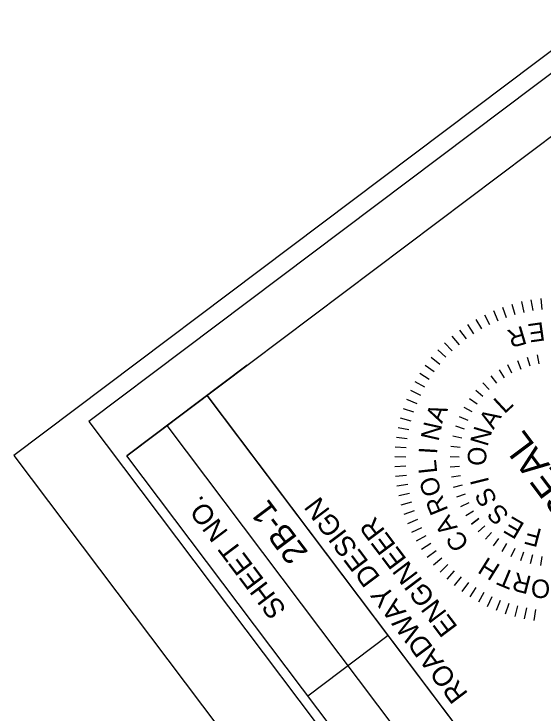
# Model space of a CAD drawing. Extents: x 1262917 to 1264804, y 775326 to 777329.
# Drawn here: x 1262916.5 to 1263048.7, y 776605.9 to 776780.7 of the extents above; entities that cross this region are included whole.
import ezdxf

# ---------------------------------------------------------------- set-up
doc = ezdxf.new("R2010")
doc.units = 0
for name, color, linetype in [('Default', 7, 'Continuous'), ('Sheet Data Field CELL', 7, 'Continuous'), ('Sheet Plan CELL', 7, 'Continuous'), ('Sheet Plot Border Inside CELL', 7, 'Continuous'), ('Sheet Plot Border Outside CELL', 7, 'Continuous'), ('Sheet Typical CELL', 7, 'Continuous')]:
    doc.layers.add(name, color=color, linetype=linetype)

msp = doc.modelspace()

# ---------------------------------------------------------------- linework, layer by layer
at = {"layer": 'Default'}
for p, q in [((1263045.47, 776709.34), (1263045.91, 776706.62)), ((1263047.9, 776709.66), (1263048.17, 776706.92)), ((1263038.38, 776707.52), (1263039.31, 776704.92)), ((1263040.7, 776708.27), (1263041.47, 776705.61)), ((1263043.07, 776708.87), (1263043.68, 776706.18)), ((1263033.88, 776705.6), (1263035.11, 776703.13)), ((1263036.09, 776706.62), (1263037.18, 776704.09)), ((1263031.72, 776704.44), (1263033.1, 776702.05)), ((1263029.64, 776703.15), (1263031.17, 776700.85)), ((1263027.65, 776701.74), (1263029.3, 776699.54)), ((1263023.92, 776698.57), (1263025.83, 776696.58)), ((1263025.73, 776700.21), (1263027.52, 776698.11)), ((1263022.21, 776696.83), (1263024.24, 776694.96)), ((1263020.61, 776694.98), (1263022.74, 776693.23)), ((1263044.55, 776695.01), (1263045.19, 776692.8)), ((1263047.05, 776695.6), (1263047.47, 776693.35)), ((1263042.11, 776694.18), (1263042.96, 776692.04)), ((1263019.11, 776693.04), (1263021.36, 776691.42)), ((1263037.53, 776691.81), (1263038.77, 776689.88)), ((1263040.74, 776691.02), (1263039.68, 776693.07)), ((1263017.75, 776691.01), (1263020.08, 776689.54)), ((1263035.43, 776690.32), (1263036.85, 776688.51)), ((1263016.51, 776688.91), (1263018.92, 776687.57)), ((1263033.49, 776688.62), (1263035.08, 776686.96)), ((1263015.39, 776686.73), (1263017.89, 776685.55)), ((1263031.71, 776686.75), (1263033.46, 776685.25)), ((1263030.13, 776684.71), (1263032.02, 776683.39)), ((1263014.41, 776684.49), (1263016.97, 776683.46)), ((1263013.57, 776682.19), (1263016.18, 776681.32)), ((1263028.75, 776682.53), (1263030.76, 776681.4)), ((1263012.86, 776679.85), (1263015.53, 776679.14)), ((1263027.59, 776680.22), (1263029.7, 776679.3)), ((1263026.66, 776677.82), (1263028.84, 776677.1)), ((1263012.3, 776677.47), (1263015.01, 776676.92)), ((1263011.89, 776675.06), (1263014.62, 776674.67)), ((1263025.96, 776675.34), (1263028.2, 776674.83)), ((1263011.62, 776672.63), (1263014.37, 776672.41)), ((1263025.51, 776672.8), (1263027.79, 776672.51)), ((1263011.49, 776670.18), (1263014.25, 776670.13)), ((1263025.3, 776670.23), (1263027.6, 776670.16)), ((1263011.52, 776667.74), (1263014.28, 776667.85)), ((1263025.34, 776667.66), (1263027.64, 776667.81)), ((1263011.69, 776665.3), (1263014.44, 776665.58)), ((1263025.64, 776665.09), (1263027.9, 776665.46)), ((1263012.01, 776662.88), (1263014.74, 776663.32)), ((1263026.17, 776662.57), (1263028.4, 776663.16)), ((1263012.48, 776660.48), (1263015.17, 776661.08)), ((1263026.95, 776660.11), (1263029.11, 776660.91)), ((1263013.09, 776658.11), (1263015.74, 776658.87)), ((1263027.96, 776657.74), (1263030.03, 776658.75)), ((1263013.83, 776655.78), (1263016.44, 776656.71)), ((1263029.2, 776655.48), (1263031.16, 776656.68)), ((1263014.73, 776653.5), (1263017.27, 776654.59)), ((1263030.65, 776653.34), (1263032.48, 776654.73)), ((1263032.48, 776654.73), (1263030.65, 776653.34)), ((1263015.75, 776651.28), (1263018.22, 776652.52)), ((1263032.29, 776651.36), (1263033.99, 776652.91)), ((1263016.92, 776649.13), (1263019.3, 776650.51)), ((1263034.12, 776649.55), (1263035.66, 776651.25)), ((1263036.12, 776647.91), (1263037.49, 776649.76)), ((1263018.2, 776647.05), (1263020.5, 776648.57)), ((1263038.26, 776646.48), (1263039.45, 776648.46)), ((1263019.61, 776645.05), (1263021.82, 776646.71)), ((1263040.54, 776645.27), (1263041.53, 776647.34)), ((1263042.92, 776644.28), (1263043.7, 776646.44)), ((1263021.14, 776643.14), (1263023.24, 776644.93)), ((1263045.39, 776643.52), (1263045.95, 776645.75)), ((1263047.91, 776643.01), (1263048.26, 776645.28)), ((1263022.78, 776641.33), (1263024.77, 776643.24)), ((1263024.53, 776639.61), (1263026.4, 776641.64)), ((1263026.37, 776638.01), (1263028.12, 776640.15)), ((1263028.31, 776636.52), (1263029.93, 776638.76)), ((1263030.34, 776635.15), (1263031.81, 776637.49)), ((1263032.45, 776633.91), (1263033.78, 776636.33)), ((1263034.62, 776632.8), (1263035.81, 776635.29)), ((1263036.87, 776631.81), (1263037.89, 776634.38)), ((1263039.16, 776630.97), (1263040.03, 776633.59)), ((1263041.5, 776630.27), (1263042.22, 776632.93)), ((1263043.88, 776629.71), (1263044.44, 776632.41)), ((1263046.29, 776629.29), (1263046.68, 776632.02))]:
    msp.add_line(p, q, dxfattribs=at)
at = {"layer": 'Sheet Plan CELL'}
msp.add_lwpolyline([(1263054.56, 776753.11), (1263133.61, 776648.16), (1263043.77, 776580.5), (1262964.72, 776685.44)], dxfattribs=at)
at = {"layer": 'Sheet Plot Border Inside CELL'}
msp.add_lwpolyline([(1264780.22, 775982.89), (1263777.88, 777313.61), (1262935.19, 776678.9), (1263937.52, 775348.16)], close=True, dxfattribs=at)
at = {"layer": 'Sheet Plot Border Outside CELL'}
msp.add_lwpolyline([(1262916.5, 776670.46), (1263929.36, 775325.74), (1264804.01, 775984.53), (1263791.15, 777329.26)], close=True, dxfattribs=at)
at = {"layer": 'Sheet Typical CELL'}
for p, q in [((1262944.69, 776670.41), (1263783.4, 777302.14)), ((1262974.7, 776693.01), (1262944.69, 776670.41)), ((1263085.07, 776525.72), (1262964.72, 776685.5)), ((1263075.06, 776518.17), (1262954.71, 776677.96)), ((1263065.04, 776510.63), (1262944.69, 776670.41)), ((1263847.15, 775472.26), (1262944.69, 776670.41)), ((1262989.84, 776610.48), (1263009.87, 776625.57))]:
    msp.add_line(p, q, dxfattribs=at)

# ---------------------------------------------------------------- texts
at = {"layer": 'Default'}
for s, height, rotation, p in [('E', 4.6, 187.9341, (1263048.58, 776703.78)), ('R', 4.6, 196.6068, (1263043.45, 776702.88)), ('L', 4.6, 42.805, (1263038.85, 776680.71)), ('A', 4.6, 67.4515, (1263023.27, 776678.31)), ('A', 4.6, 58.1013, (1263036.11, 776676.78)), ('N', 4.6, 77.219, (1263022.38, 776673.84)), ('N', 4.6, 73.3975, (1263034.61, 776672.51)), ('SEAL', 6.899, 126.9344, (1263057.75, 776658.25)), ('O', 4.6, 88.6938, (1263034.28, 776667.83)), ('I', 4.6, 86.5135, (1263022.03, 776670.7)), ('L', 4.6, 96.089, (1263022.12, 776666.13)), ('O', 4.6, 109.2252, (1263023.3, 776661.17)), ('I', 4.6, 103.99, (1263035.08, 776663.79)), ('S', 4.6, 119.2863, (1263037.22, 776659.29)), ('R', 4.6, 112.2821, (1263024.91, 776656.81)), ('S', 4.6, 134.5825, (1263040.28, 776655.85)), ('A', 4.6, 124.2914, (1263027.3, 776652.51)), ('E', 4.6, 149.8788, (1263044.14, 776653.35)), ('C', 4.6, 124.2914, (1263030.24, 776648.44)), ('F', 4.6, 165.175, (1263048.43, 776651.97)), ('H', 4.6, 148.0021, (1263038.1, 776642.91)), ('T', 4.6, 157.434, (1263041.92, 776641.15)), ('R', 4.6, 165.595, (1263045.84, 776640.23)), ('O', 4.6, 178.6517, (1263050.31, 776639.43))]:
    msp.add_text(s, height=height, rotation=rotation, dxfattribs=at).set_placement(p)
at = {"layer": 'Sheet Data Field CELL'}
msp.add_text('2B-1', height=6, rotation=126.9874, dxfattribs=at).set_placement((1262990.06, 776646.27))
at = {"layer": 'Sheet Plan CELL'}
for s, height, p in [('SHEET NO.', 5, (1262984.64, 776632.04)), ('ROADWAY DESIGN', 4.9986, (1263029.94, 776610.99)), ('ENGINEER', 4.999, (1263027.36, 776627.63))]:
    msp.add_text(s, height=height, rotation=126.9874, dxfattribs=at).set_placement(p)

doc.saveas('drawing.dxf')
